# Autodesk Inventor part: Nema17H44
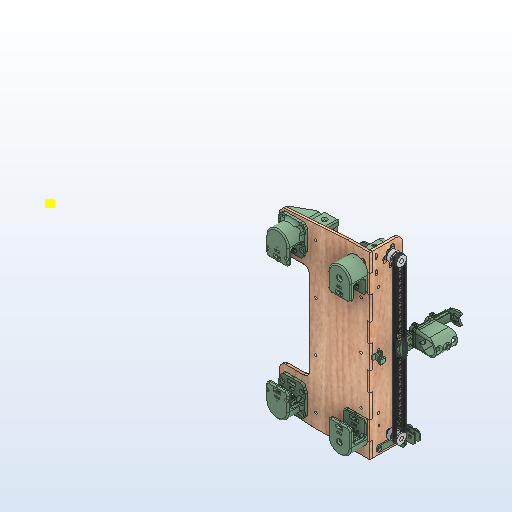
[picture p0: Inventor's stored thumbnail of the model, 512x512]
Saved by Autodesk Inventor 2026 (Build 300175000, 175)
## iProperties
Created: 2025-11
Part Number: Nema17H44
Material: Steel
Document SubType Name: Modeling
Designer: Yury Melnikov
Density: 7.85 g/cm^3
Appearance: Резина — зеленая
Mass: 34859.8 g
Surface Area: 7325.72 cm^2
Volume: 4440.74 cm^3
Sending System: Autodesk Translation Framework v14.17.0.0
Preprocessor: ST-DEVELOPER v20.1
Title: m2_20.step
## Parameters: d0 = 504 deg, d1 = 12.56644 mm, d2 = 201.062 mm, d3 = 16 mm, d4 = 72 deg, d5 = 16 mm, d8 = 0, d11 = 201 mm, d14 = 16 mm, d15 = 0, d16 = 16 mm, d18 = 30.5 mm, d19 = 30.5 mm, d22 = 30.5 mm, d25 = 30.5 mm, d28 = 3.3 mm, d29 = 4.8 mm, d30 = 4.8 mm, d31 = 4.8 mm, d32 = 4.8 mm, d33 = 16 mm, d37 = 2.348 mm, d38 = 2.348 mm, d40 = 0, d42 = 8.1 mm, d43 = 8.1 mm, d44 = 5.9 mm, d45 = 5.9 mm, d47 = 0, d52 = 8 mm, d53 = 4 mm, d55 = 5 mm, d56 = 11 mm, d57 = 12.2 mm, d58 = 6.1 mm, d60 = 36 mm, d61 = 45 mm, d63 = 8.1 mm, d64 = 5 mm, d65 = 3 mm, d66 = 5.7 mm, d67 = 4 mm, d68 = 0, d70 = 3 mm, d72 = 213.75 mm, d73 = 0, d74 = 1 mm, d75 = 2 mm, d76 = 45 deg, d77 = 22 mm, d78 = 1 mm, d80 = 16 mm, d81 = 8 mm, d82 = 12 mm, d84 = 213.75 mm, d85 = 0, d86 = 2 mm, d92 = 360 deg, d94 = 4 mm, d95 = 5 mm, d96 = 0, d97 = 0.7 mm, d98 = 2 mm, d99 = 45 deg, d100 = 31.1 mm, d101 = 31.1 mm, d102 = 42 mm, d103 = 44 mm, d106 = 31.1 mm, d109 = 31.1 mm, d112 = 3.3 mm, d113 = 4.8 mm, d114 = 4.8 mm, d115 = 4.8 mm, d116 = 4.8 mm, d117 = 4.8 mm, d118 = 4.8 mm, d119 = 4.8 mm, d120 = 4.8 mm, d121 = 4 mm, d122 = 0, d123 = 5 mm, d124 = 4 mm, d125 = 0, d126 = 2 mm, d127 = 2 mm, d128 = 45 deg, d129 = 3 mm, d130 = 3 mm, d131 = 2 mm, d132 = 2 mm, d133 = 24 mm, d134 = 2.8 mm, d135 = 2.8 mm, d138 = 6 mm, d139 = 6 mm, d140 = 4 mm, d141 = 0, d145 = 1 mm, d146 = 2 mm, d147 = 45 deg, d149 = 4 mm, d150 = 0, d154 = 1 mm, d155 = 2 mm, d156 = 45 deg, d157 = 105 mm, d158 = 45 mm, d160 = 0, d161 = 3 mm, d162 = 2 mm, d163 = 45 deg, d165 = 9.25 mm, d166 = 18 mm, d168 = 31 mm, d169 = 44 mm, d171 = 16 mm, d172 = 8 mm, d173 = 14 mm, d176 = 0, d179 = 16 mm, d180 = 0, d182 = 2 mm, d183 = 8 mm, d187 = 3 mm, d188 = 22.4 mm, d190 = 3 mm, d191 = 3 mm, d192 = 4 mm, d193 = 16 mm, d194 = 16 mm, d195 = 5 mm, d197 = 3 mm, d198 = 2 mm, d199 = 6 mm, d200 = 90 deg, d201 = 26 mm, d202 = 16 mm, d203 = 2 mm, d204 = 6 mm, d205 = 247 mm, d206 = 90 deg, d207 = 9.1 mm, d208 = 24 mm, d209 = 3 mm, d210 = 31.1 mm, d213 = 31.1 mm, d216 = 31.1 mm, d219 = 43 mm, d220 = 43 mm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
